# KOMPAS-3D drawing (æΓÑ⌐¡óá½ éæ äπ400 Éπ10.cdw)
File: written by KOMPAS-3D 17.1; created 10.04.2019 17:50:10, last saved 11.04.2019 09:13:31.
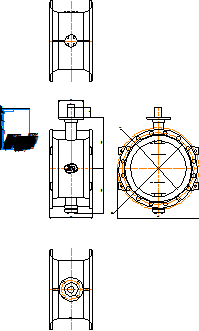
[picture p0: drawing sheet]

Sheet 1: A4, portrait

Title block, sheet 1: name: Стейнвал ВС Ду400 Ру10; material: Внимание! Данный продукт является объектом авторского права ООО «Торговый Дом АДЛ». / Запрещается изменение, копирование, распространение / (в том числе путем копирования на другие сайты и ресурсы в Интернете) / или любое иное использование информации и объектов без предварительного / согласия правообладателя (ООО «Торговый Дом АДЛ»).; mass: 126,28; sheets: 1; organisation: ООО "Торговый дом АДЛ"; sheet format: A4; stored path: \\adlc.lan\data\АДЛ_ПКД\3D-модели\ADL production\Дисковые поворотные затворы СТЕЙНВАЛ\Двухэксцентриковый ВС\KOMPAS 2D\Стейнвал ВС Ду400 Ру10.cdw

Views: Вид 1, Проекционный вид 4
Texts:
  user
Dimensions and other numbers on the sheet: 50; 175; 367; 320; 70; 302; 515; 400; 586,98; 1:1; 1; 126,28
